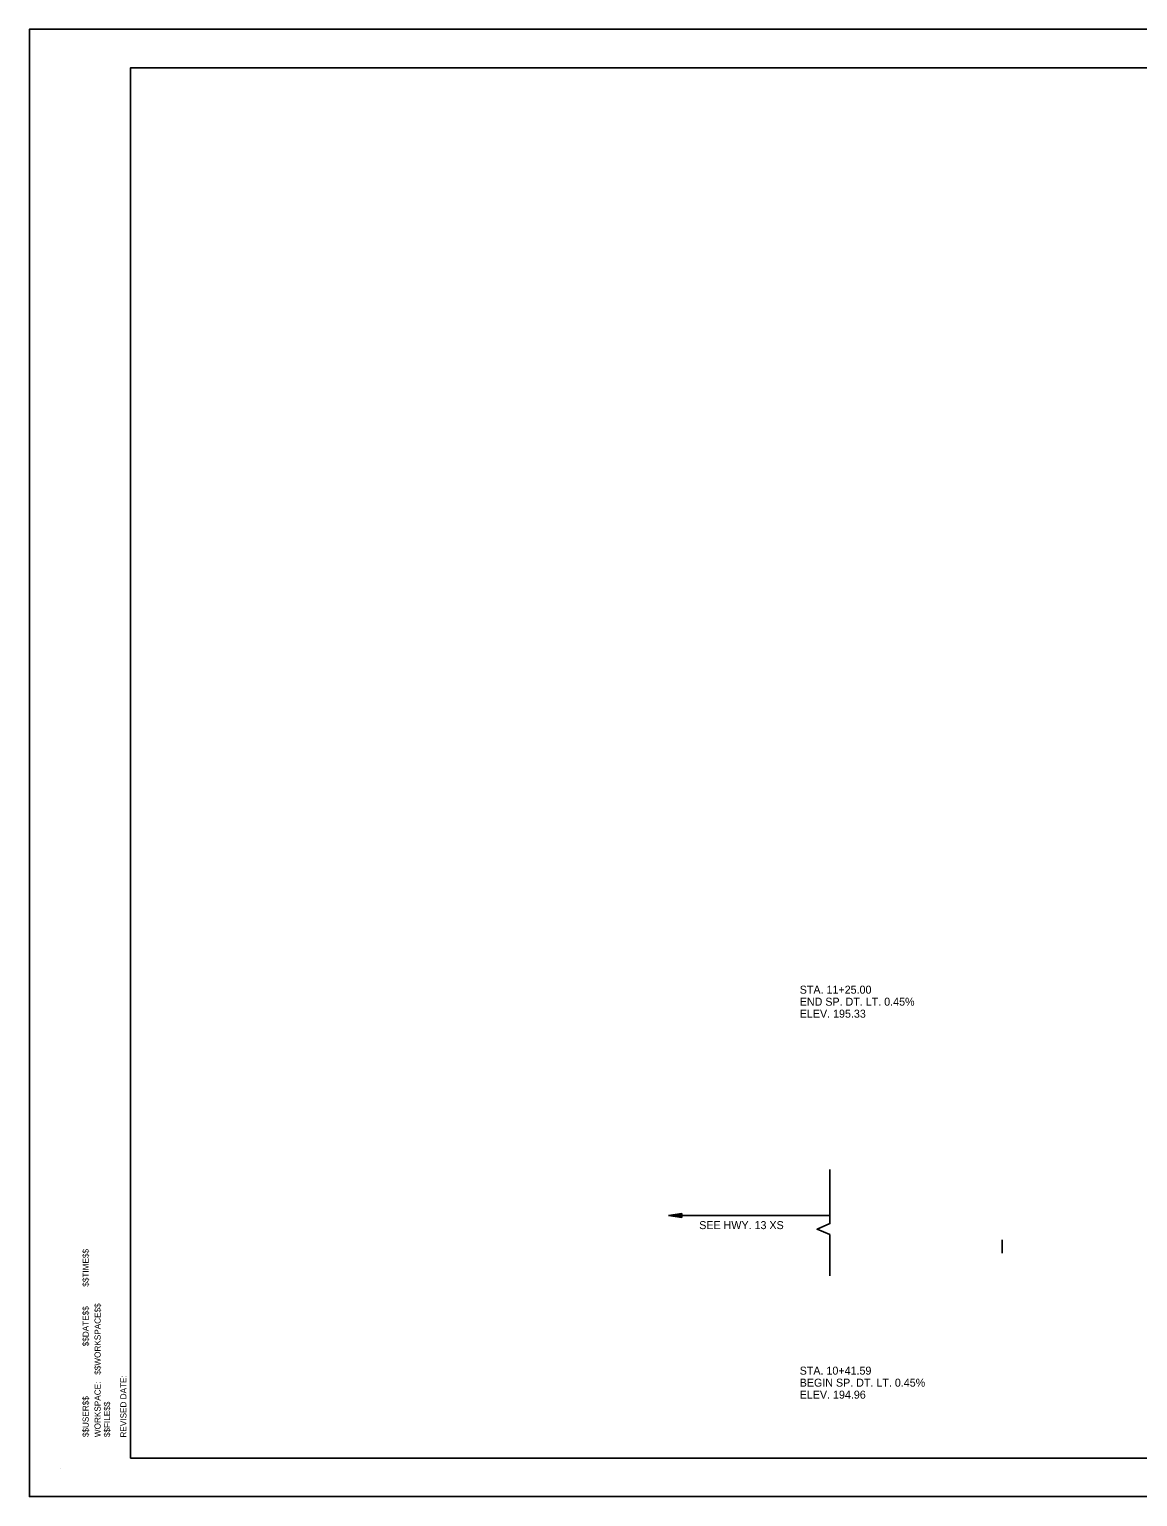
# Model space of a CAD drawing. Extents: x 1284907 to 1285667, y 403630 to 403851.
# Drawn here: x 1284907.4 to 1285073.5, y 403631.1 to 403851.1 of the extents above; entities that cross this region are included whole.
import ezdxf

# ---------------------------------------------------------------- set-up
doc = ezdxf.new("R2010")
doc.units = 0
for name, color, linetype in [('1', 7, 'Continuous'), ('8', 7, 'Continuous'), ('Default', 7, 'Continuous'), ('R_Draft', 7, 'Continuous'), ('R_Vert Alg Annot_Drive', 7, 'Continuous')]:
    doc.layers.add(name, color=color, linetype=linetype)

msp = doc.modelspace()

# ---------------------------------------------------------------- linework, layer by layer
at = {"layer": '1'}
for p, q in [((1284922.56, 403845.32), (1285241.63, 403845.32)), ((1284922.56, 403636.85), (1284922.56, 403845.32)), ((1285241.63, 403636.85), (1284922.56, 403636.85)), ((1284912.08, 403635.37), (1284912.08, 403635.37))]:
    msp.add_line(p, q, dxfattribs=at)
for points in [[(1285247.4, 403851.09), (1284907.4, 403851.09), (1284907.4, 403631.09), (1285247.4, 403631.09)], [(1284922.56, 403636.85), (1284922.56, 403845.32), (1285159.37, 403845.32), (1285159.37, 403835.44), (1285198.53, 403835.44), (1285198.53, 403832.52), (1285241.63, 403832.52), (1285241.63, 403636.85)]]:
    msp.add_lwpolyline(points, close=True, dxfattribs=at)
at = {"layer": 'Default'}
msp.add_line((1285053.21, 403669.6), (1285053.21, 403667.6), dxfattribs=at)
at = {"layer": 'R_Draft'}
for p, q in [((1285005.19, 403673.53), (1285003.19, 403673.23)), ((1285005.19, 403672.93), (1285003.19, 403673.23)), ((1285005.19, 403673.48), (1285003.53, 403673.23)), ((1285005.19, 403672.98), (1285003.53, 403673.23)), ((1285005.19, 403673.43), (1285003.87, 403673.23)), ((1285005.19, 403673.03), (1285003.87, 403673.23)), ((1285005.19, 403673.38), (1285004.2, 403673.23)), ((1285005.19, 403673.08), (1285004.2, 403673.23)), ((1285005.19, 403673.33), (1285004.54, 403673.23)), ((1285005.19, 403673.13), (1285004.54, 403673.23)), ((1285005.19, 403673.28), (1285004.88, 403673.23)), ((1285005.19, 403673.18), (1285004.88, 403673.23)), ((1285005.19, 403672.93), (1285005.19, 403673.53)), ((1285027.4, 403670.4), (1285027.39, 403664.2))]:
    msp.add_line(p, q, dxfattribs=at)
msp.add_lwpolyline([(1285027.4, 403680.16), (1285027.4, 403672.02), (1285025.48, 403671.18), (1285027.4, 403670.4)], dxfattribs=at)
at = {"layer": 'R_Vert Alg Annot_Drive'}
msp.add_line((1285027.4, 403673.23), (1285003.19, 403673.23), dxfattribs=at)

# ---------------------------------------------------------------- texts
at = {"layer": '1'}
for s, p in [('$$TIME$$', (1284916.29, 403662.56)), ('$$DATE$$', (1284916.29, 403653.63)), ('$$WORKSPACE$$', (1284918.08, 403649.36)), ('WORKSPACE:', (1284918.08, 403640.01)), ('REVISED DATE:', (1284921.95, 403639.95)), ('$$USER$$', (1284916.29, 403640.01)), ('$$FILE$$', (1284919.5, 403640.01))]:
    msp.add_text(s, height=0.918, rotation=90, dxfattribs=at).set_placement(p)
at = {"layer": '8'}
for s, p in [('STA. 11+25.00', (1285022.88, 403706.5)), ('END SP. DT. LT. 0.45%', (1285022.88, 403704.7)), ('ELEV. 195.33', (1285022.88, 403702.9)), ('STA. 10+41.59', (1285022.87, 403649.38)), ('BEGIN SP. DT. LT. 0.45%', (1285022.87, 403647.58)), ('ELEV. 194.96', (1285022.87, 403645.78))]:
    msp.add_text(s, height=1.2, dxfattribs=at).set_placement(p)
at = {"layer": 'R_Vert Alg Annot_Drive'}
msp.add_text('SEE HWY. 13 XS', height=1.2, dxfattribs=at).set_placement((1285007.81, 403671.2))

doc.saveas('drawing.dxf')
